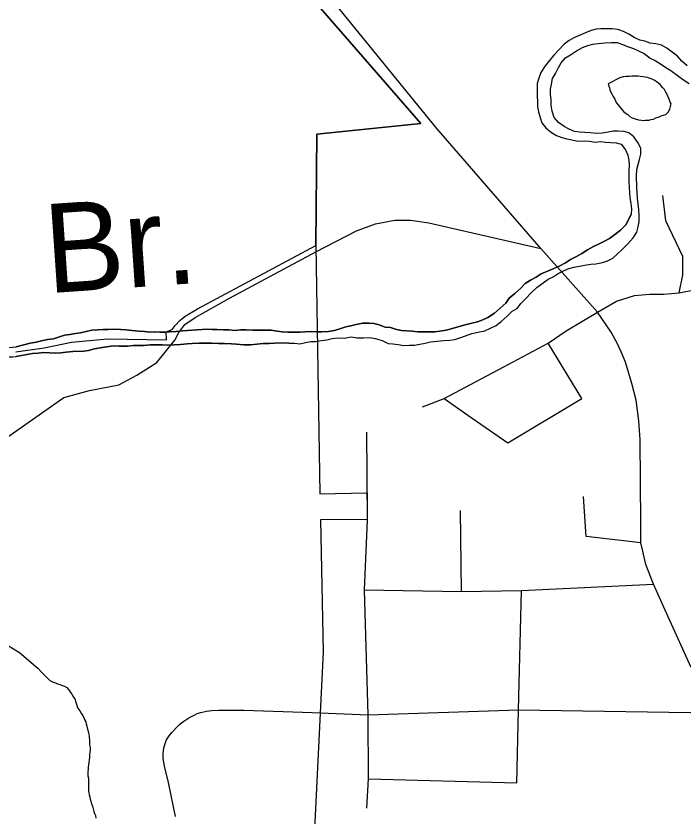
# Model space of a CAD drawing. Extents: x 0 to 44.3, y 0 to 22.
# Drawn here: x 6.753 to 7.465, y 17.047 to 17.9 of the extents above; entities that cross this region are included whole.
import ezdxf

# ---------------------------------------------------------------- set-up
doc = ezdxf.new("R2010")
doc.units = 0
for name, color, linetype in [('GM_X_City_Street', 7, 'Continuous'), ('GM_X_Corporation', 7, 'Continuous'), ('GM_X_Minor_Lake', 7, 'Continuous'), ('GM_X_Minor_River', 7, 'Continuous'), ('GM_X_Minor_River_Text', 7, 'Continuous'), ('GM_X_State_Route', 7, 'Continuous')]:
    doc.layers.add(name, color=color, linetype=linetype)

msp = doc.modelspace()

# ---------------------------------------------------------------- linework, layer by layer
at = {"layer": 'GM_X_City_Street'}
for p, q in [((7.12724, 17.41122), (7.12695, 17.45623)), ((7.22768, 17.28648), (7.22658, 17.37258)), ((7.12878, 17.08658), (7.28653, 17.0823))]:
    msp.add_line(p, q, dxfattribs=at)
for points in [[(7.45977, 17.60465), (7.46347, 17.62393), (7.46345, 17.64339), (7.44532, 17.68153), (7.44219, 17.70849)], [(7.07246, 17.64827), (7.11592, 17.67067), (7.13597, 17.67813), (7.15675, 17.68201), (7.17336, 17.68207), (7.19293, 17.67924), (7.31218, 17.65183)], [(6.92212, 17.55418), (6.92659, 17.5623), (6.93286, 17.57103), (6.94381, 17.57832), (6.98068, 17.59888), (7.07246, 17.64827)], [(7.18604, 17.48326), (7.20918, 17.49199), (7.27207, 17.52551), (7.31997, 17.55123), (7.33909, 17.56424), (7.37276, 17.584)], [(6.30242, 16.8069), (6.63737, 17.15584), (6.69056, 17.36679), (6.69333, 17.3776), (6.70222, 17.39979), (6.7063, 17.40894), (6.71111, 17.41764), (6.72202, 17.43335), (6.72813, 17.44047), (6.73703, 17.44625), (6.80414, 17.49308), (6.83121, 17.5006), (6.86241, 17.50669), (6.88169, 17.51703), (6.90323, 17.53033), (6.92212, 17.55418)], [(7.20918, 17.49199), (7.23431, 17.47423), (7.27695, 17.4449), (7.35592, 17.49195), (7.31997, 17.55123)], [(7.12741, 17.37786), (7.12737, 17.39097), (7.12724, 17.41122)], [(7.41896, 17.33821), (7.36072, 17.34509), (7.35764, 17.38766)], [(7.12695, 17.05542), (7.12878, 17.08658), (7.12817, 17.15502), (7.1245, 17.28821), (7.12746, 17.36257), (7.12741, 17.37786)], [(7.1245, 17.28821), (7.22768, 17.28648), (7.29178, 17.28762), (7.43229, 17.29421)], [(7.28653, 17.0823), (7.28852, 17.16019), (7.29178, 17.28762)], [(6.92286, 17.04654), (6.91542, 17.08269), (6.91132, 17.1002), (6.90967, 17.10849), (6.90986, 17.11364), (6.91065, 17.11967), (6.91257, 17.12643), (6.91308, 17.12754), (6.91415, 17.12949), (6.91619, 17.1325), (6.91911, 17.136), (6.92534, 17.14281), (6.9271, 17.14466), (6.92933, 17.14641), (6.93186, 17.14826), (6.93732, 17.15185), (6.94344, 17.15507), (6.94612, 17.15628), (6.94997, 17.15759), (6.9559, 17.1588), (6.96164, 17.15953), (6.96874, 17.15996), (6.99625, 17.15983), (7.06866, 17.15732)], [(7.06866, 17.15732), (7.12817, 17.15502), (7.28852, 17.16019), (7.49466, 17.15689)]]:
    msp.add_lwpolyline(points, dxfattribs=at)
at = {"layer": 'GM_X_Corporation'}
for points in [[(7.82586, 18.31414), (6.89604, 18.28498), (6.92603, 18.24781), (6.94991, 18.15965), (6.96334, 18.1059), (6.94492, 18.09718), (6.93169, 18.09094), (6.92822, 17.95203), (7.03936, 17.95213), (7.18428, 17.78522), (7.07361, 17.77392), (7.07233, 17.65528), (7.07678, 17.3906), (7.12716, 17.39153), (7.12726, 17.36313), (7.07741, 17.36275), (7.08028, 17.22203), (7.07018, 17.01142)], [(6.75287, 17.54169), (6.78294, 17.54612), (6.81197, 17.55215), (6.85066, 17.55576), (6.91324, 17.55458), (6.91296, 17.5631), (6.91953, 17.56556), (6.92257, 17.56982), (6.92761, 17.57513), (6.93342, 17.58001), (6.94645, 17.58759), (7.07233, 17.65528), (7.07361, 17.77392), (7.18428, 17.78522), (7.03936, 17.95213)], [(6.75287, 17.54169), (6.78294, 17.54612), (6.81197, 17.55215), (6.85066, 17.55576), (6.91324, 17.55458), (6.91296, 17.5631), (6.91953, 17.56556), (6.92257, 17.56982), (6.92761, 17.57513), (6.93342, 17.58001), (6.94645, 17.58759), (7.07233, 17.65528), (7.07678, 17.3906), (7.12716, 17.39153), (7.12726, 17.36313), (7.07741, 17.36275), (7.08028, 17.22203), (7.07018, 17.01142)]]:
    msp.add_lwpolyline(points, dxfattribs=at)
at = {"layer": 'GM_X_Minor_Lake'}
for points in [[(7.39241, 17.80765), (7.40044, 17.79793), (7.40316, 17.79572), (7.40509, 17.79462), (7.40704, 17.79277), (7.40975, 17.79132), (7.41282, 17.79025), (7.41628, 17.7892), (7.41971, 17.7889), (7.42163, 17.78857), (7.42353, 17.78862), (7.42543, 17.78867), (7.42772, 17.78873), (7.4296, 17.78954), (7.43226, 17.78999), (7.43489, 17.79119), (7.43829, 17.79242), (7.44056, 17.79324), (7.44282, 17.79406), (7.44547, 17.79489), (7.44807, 17.79724), (7.4499, 17.80033), (7.45128, 17.80608), (7.45008, 17.80796), (7.44886, 17.81097), (7.44803, 17.81361), (7.44722, 17.8155), (7.44562, 17.8185), (7.44402, 17.82151), (7.44206, 17.82374), (7.43932, 17.82672), (7.43504, 17.83003), (7.4331, 17.83151), (7.43001, 17.83295), (7.42771, 17.83366), (7.42579, 17.83437), (7.42387, 17.8347), (7.4212, 17.83502), (7.41814, 17.83532), (7.41547, 17.83563), (7.41242, 17.83555), (7.40938, 17.83547), (7.40633, 17.8354), (7.40329, 17.83532), (7.39987, 17.83485), (7.39646, 17.834), (7.38406, 17.8276)], [(7.38406, 17.8276), (7.38448, 17.82608), (7.38532, 17.82306), (7.38575, 17.82117), (7.38696, 17.81853), (7.38816, 17.81628), (7.38936, 17.81402), (7.39096, 17.81102), (7.39241, 17.80765)]]:
    msp.add_lwpolyline(points, dxfattribs=at)
at = {"layer": 'GM_X_Minor_River'}
for points in [[(7.46828, 17.84656), (7.46257, 17.85148), (7.45801, 17.85679), (7.45231, 17.86133), (7.4466, 17.86549), (7.44091, 17.86852), (7.43483, 17.87002), (7.42876, 17.87076), (7.42307, 17.87303), (7.41776, 17.87415), (7.41168, 17.8768), (7.40598, 17.88058), (7.40028, 17.88323), (7.39421, 17.88549), (7.38814, 17.88624), (7.37638, 17.88621), (7.37107, 17.88581), (7.36577, 17.88428), (7.35971, 17.88199), (7.34759, 17.87664), (7.34229, 17.87359), (7.33699, 17.86978), (7.3317, 17.86408), (7.32602, 17.85799), (7.31695, 17.84657), (7.31242, 17.83973), (7.31017, 17.83365), (7.30828, 17.82795), (7.30832, 17.81428), (7.30872, 17.8082), (7.30874, 17.80289), (7.30989, 17.79758), (7.31142, 17.7915), (7.31333, 17.78581), (7.31752, 17.78051), (7.3236, 17.77558), (7.32892, 17.77256), (7.33462, 17.77029), (7.33993, 17.76879), (7.35207, 17.76654), (7.35852, 17.76656), (7.36421, 17.76619), (7.37028, 17.76545), (7.37597, 17.76584), (7.38128, 17.76547), (7.39266, 17.76474), (7.39797, 17.76323), (7.40254, 17.75717), (7.40483, 17.75148), (7.40599, 17.74617), (7.40638, 17.74085), (7.40602, 17.73515), (7.40605, 17.723), (7.40724, 17.70592), (7.40802, 17.69985), (7.40879, 17.69415), (7.40843, 17.68846)], [(7.32458, 17.8333), (7.32797, 17.83863), (7.33099, 17.84471), (7.33401, 17.85003), (7.33855, 17.85536), (7.34385, 17.85841), (7.35028, 17.8626), (7.35672, 17.86603), (7.3624, 17.86833), (7.36771, 17.86986), (7.37339, 17.87063), (7.3806, 17.87103), (7.38742, 17.87142), (7.39349, 17.87144), (7.39919, 17.86955), (7.40564, 17.86691), (7.41096, 17.86503), (7.41703, 17.86238), (7.42235, 17.85974), (7.42881, 17.85482), (7.43413, 17.85217), (7.43983, 17.84877), (7.44553, 17.84499), (7.45085, 17.84158), (7.45769, 17.83666), (7.46339, 17.8325), (7.47023, 17.82796)], [(7.0436, 17.55089), (7.04967, 17.5509), (7.05536, 17.55053), (7.06142, 17.55169), (7.06711, 17.55284), (7.07242, 17.55285), (7.07848, 17.55401), (7.08417, 17.55478), (7.08985, 17.55593), (7.09592, 17.55671), (7.10313, 17.55635), (7.11033, 17.55788), (7.1164, 17.55676), (7.12323, 17.55677), (7.13005, 17.55717), (7.13574, 17.55604), (7.14333, 17.55378), (7.14941, 17.55076), (7.15472, 17.55039), (7.16041, 17.54965), (7.16611, 17.54852), (7.17179, 17.54892), (7.17748, 17.54893), (7.18317, 17.55008), (7.18885, 17.55124), (7.19454, 17.55239), (7.20895, 17.55394), (7.21539, 17.55434), (7.2207, 17.55511), (7.226, 17.55664), (7.23207, 17.55893), (7.23889, 17.56123), (7.24685, 17.56314), (7.25253, 17.5643), (7.25859, 17.56697), (7.26465, 17.57002), (7.26995, 17.57421), (7.27638, 17.57992), (7.28167, 17.58525), (7.28698, 17.58792), (7.29113, 17.59325), (7.29643, 17.59858), (7.3021, 17.60467), (7.30853, 17.61076), (7.31458, 17.61533), (7.32026, 17.61914), (7.32556, 17.62181), (7.33086, 17.62524), (7.33654, 17.62829), (7.34222, 17.63058), (7.34753, 17.63211), (7.3536, 17.63327), (7.3589, 17.63404), (7.36572, 17.63519), (7.37103, 17.63559), (7.37785, 17.63712), (7.38316, 17.63865), (7.38884, 17.64171), (7.39414, 17.64628), (7.39943, 17.65122), (7.4051, 17.65693), (7.41078, 17.6634), (7.41455, 17.66949), (7.41605, 17.67519), (7.41717, 17.6805), (7.41716, 17.68696), (7.41676, 17.69303), (7.41598, 17.69949), (7.41521, 17.70556), (7.41481, 17.71164), (7.41442, 17.71695), (7.41438, 17.72948), (7.41474, 17.73632), (7.41586, 17.74163), (7.41736, 17.74695), (7.41886, 17.75265), (7.41885, 17.75873), (7.41579, 17.76479), (7.41123, 17.77086), (7.4059, 17.7754), (7.40059, 17.77653), (7.39452, 17.77689), (7.38921, 17.77688), (7.3839, 17.77611), (7.37746, 17.77496), (7.37139, 17.77456), (7.36532, 17.77531), (7.35925, 17.77567), (7.35356, 17.77604), (7.34825, 17.77678), (7.34256, 17.77905), (7.33724, 17.78207), (7.33116, 17.78624), (7.32659, 17.79154), (7.3243, 17.79837), (7.32314, 17.80482), (7.32313, 17.81052), (7.32273, 17.81659), (7.32271, 17.82191), (7.32346, 17.82723), (7.32458, 17.8333)], [(7.40843, 17.68846), (7.40579, 17.68238), (7.40277, 17.67705), (7.3971, 17.67134), (7.39104, 17.66677), (7.38537, 17.66258), (7.37931, 17.65953), (7.37363, 17.65648), (7.36832, 17.65419), (7.36189, 17.65037), (7.35583, 17.64656), (7.35015, 17.64351), (7.34371, 17.64008), (7.33842, 17.63665), (7.33198, 17.63321), (7.32554, 17.63016), (7.31266, 17.62482), (7.30736, 17.62139), (7.3013, 17.61833), (7.29562, 17.61452), (7.29071, 17.6092), (7.28465, 17.60386), (7.2786, 17.59891), (7.27482, 17.59359), (7.26272, 17.58293), (7.2559, 17.57836), (7.2506, 17.57606), (7.24492, 17.57377), (7.23885, 17.57224), (7.23014, 17.57032), (7.22407, 17.56841), (7.21763, 17.56687), (7.21157, 17.56496), (7.20475, 17.5638), (7.19944, 17.56303), (7.18161, 17.56299), (7.17479, 17.56373), (7.16948, 17.5641), (7.16378, 17.56446), (7.15847, 17.56559), (7.15202, 17.56785), (7.14633, 17.56822), (7.13987, 17.57048), (7.13418, 17.57199), (7.12887, 17.57235), (7.12242, 17.57234), (7.1156, 17.5708), (7.10992, 17.56965), (7.10461, 17.5685), (7.09931, 17.56659), (7.09249, 17.56467), (7.08604, 17.56352), (7.07884, 17.56312), (7.07353, 17.56311), (7.0667, 17.56347), (7.06063, 17.56308), (7.05532, 17.56268), (7.04281, 17.56265), (7.03674, 17.56302), (7.03143, 17.56377), (7.02498, 17.56489), (7.00526, 17.56484), (6.99805, 17.56521), (6.99236, 17.56519), (6.98667, 17.56442), (6.97984, 17.56516), (6.97416, 17.56515), (6.96733, 17.56551), (6.96202, 17.5655), (6.95633, 17.56586), (6.93585, 17.56468), (6.93054, 17.56428), (6.92372, 17.56351), (6.91689, 17.56311), (6.91159, 17.56272), (6.90628, 17.56271), (6.90097, 17.56307), (6.89566, 17.56268), (6.88997, 17.56343), (6.8839, 17.56379), (6.87669, 17.56453), (6.87024, 17.56528), (6.86455, 17.56564), (6.85696, 17.566), (6.85128, 17.56561), (6.84597, 17.5656), (6.84028, 17.56521), (6.83383, 17.56481), (6.82777, 17.56366), (6.82171, 17.56212), (6.8164, 17.56135), (6.81033, 17.5602), (6.80465, 17.55943), (6.79821, 17.55751), (6.7929, 17.5556), (6.78646, 17.55482), (6.78001, 17.55367), (6.77433, 17.55214), (6.76826, 17.55098), (6.753, 17.54701)], [(6.7532, 17.54706), (6.76826, 17.55098), (6.77433, 17.55214), (6.78001, 17.55367), (6.78646, 17.55482), (6.7929, 17.5556), (6.79821, 17.55751), (6.80465, 17.55943), (6.81033, 17.5602), (6.8164, 17.56135), (6.82171, 17.56212), (6.82777, 17.56366), (6.83383, 17.56481), (6.84028, 17.56521), (6.84597, 17.5656), (6.85128, 17.56561), (6.85696, 17.566), (6.86455, 17.56564), (6.87024, 17.56528), (6.87669, 17.56453), (6.8839, 17.56379), (6.88997, 17.56343), (6.89566, 17.56268), (6.90097, 17.56307), (6.90628, 17.56271), (6.91159, 17.56272), (6.91689, 17.56311), (6.92372, 17.56351), (6.93054, 17.56428), (6.93585, 17.56468), (6.95633, 17.56586), (6.96202, 17.5655), (6.96733, 17.56551), (6.97416, 17.56515), (6.97984, 17.56516), (6.98667, 17.56442), (6.99236, 17.56519), (6.99805, 17.56521), (7.00526, 17.56484), (7.02498, 17.56489), (7.03143, 17.56377), (7.03674, 17.56302), (7.04281, 17.56265), (7.05532, 17.56268), (7.06063, 17.56308), (7.0667, 17.56347), (7.07353, 17.56311), (7.07884, 17.56312), (7.08604, 17.56352), (7.09249, 17.56467), (7.09931, 17.56659), (7.10461, 17.5685), (7.10992, 17.56965), (7.1156, 17.5708), (7.12242, 17.57234), (7.12887, 17.57235), (7.13418, 17.57199), (7.13987, 17.57048), (7.14633, 17.56822), (7.15202, 17.56785), (7.15847, 17.56559), (7.16378, 17.56446), (7.16948, 17.5641), (7.17479, 17.56373), (7.18161, 17.56299), (7.19944, 17.56303), (7.20475, 17.5638), (7.21157, 17.56496), (7.21763, 17.56687), (7.22407, 17.56841), (7.23014, 17.57032), (7.23885, 17.57224), (7.24492, 17.57377), (7.2506, 17.57606), (7.2559, 17.57836), (7.26272, 17.58293), (7.27482, 17.59359), (7.2786, 17.59891), (7.28465, 17.60386), (7.29071, 17.6092), (7.29562, 17.61452), (7.3013, 17.61833), (7.30736, 17.62139), (7.31266, 17.62482), (7.32554, 17.63016), (7.33198, 17.63321), (7.33842, 17.63665), (7.34371, 17.64008), (7.35015, 17.64351), (7.35583, 17.64656), (7.36189, 17.65037), (7.36832, 17.65419), (7.37363, 17.65648), (7.37931, 17.65953), (7.38537, 17.66258), (7.39104, 17.66677), (7.3971, 17.67134), (7.40277, 17.67705), (7.40579, 17.68238), (7.40843, 17.68846)], [(6.75298, 17.53682), (6.77057, 17.53998), (6.77664, 17.54037), (6.7827, 17.54115), (6.78877, 17.54078), (6.79522, 17.54042), (6.80091, 17.54081), (6.80659, 17.54158), (6.81342, 17.54236), (6.82479, 17.54239), (6.8301, 17.54316), (6.83654, 17.54507), (6.84488, 17.54661), (6.85702, 17.54816), (6.86308, 17.54779), (6.87181, 17.54781), (6.87787, 17.54859), (6.88887, 17.54861), (6.89607, 17.54939), (6.90252, 17.54941), (6.90859, 17.54942), (6.91466, 17.54906), (6.92148, 17.54945), (6.92831, 17.54947), (6.93551, 17.55025), (6.94082, 17.55064), (6.94803, 17.55103), (6.9613, 17.55107), (6.96889, 17.55071), (6.97533, 17.55072), (6.98254, 17.55036), (6.98785, 17.54999), (6.99582, 17.54925), (7.00302, 17.54927), (7.00947, 17.55004), (7.01629, 17.55082), (7.02274, 17.55083), (7.02881, 17.55123), (7.03564, 17.55125), (7.0436, 17.55089)], [(7.0436, 17.55089), (7.03564, 17.55125), (7.02881, 17.55123), (7.02274, 17.55083), (7.01629, 17.55082), (7.00947, 17.55004), (7.00302, 17.54927), (6.99582, 17.54925), (6.98785, 17.54999), (6.98254, 17.55036), (6.97533, 17.55072), (6.96889, 17.55071), (6.9613, 17.55107), (6.94803, 17.55103), (6.94082, 17.55064), (6.93551, 17.55025), (6.92831, 17.54947), (6.92148, 17.54945), (6.91466, 17.54906), (6.90859, 17.54942), (6.90252, 17.54941), (6.89607, 17.54939), (6.88887, 17.54861), (6.87787, 17.54859), (6.87181, 17.54781), (6.86308, 17.54779), (6.85702, 17.54816), (6.84488, 17.54661), (6.83654, 17.54507), (6.8301, 17.54316), (6.82479, 17.54239), (6.81342, 17.54236), (6.80659, 17.54158), (6.80091, 17.54081), (6.79522, 17.54042), (6.78877, 17.54078), (6.7827, 17.54115), (6.77664, 17.54037), (6.77057, 17.53998), (6.75333, 17.53688)], [(6.73546, 17.23416), (6.75668, 17.22139)], [(6.75668, 17.22139), (6.77614, 17.20476), (6.7804, 17.19988), (6.78504, 17.19539), (6.7889, 17.19164), (6.79196, 17.19016), (6.79502, 17.18907), (6.79732, 17.18796), (6.79961, 17.18723), (6.80152, 17.1865), (6.80458, 17.18541), (6.80726, 17.18393), (6.80998, 17.18054), (6.81115, 17.17866), (6.81232, 17.17678), (6.81427, 17.17376), (6.81582, 17.17188), (6.81664, 17.16847), (6.81743, 17.1662), (6.81823, 17.16393), (6.81902, 17.16204), (6.82097, 17.15903), (6.82292, 17.15602), (6.82409, 17.15413), (6.82566, 17.15111), (6.82645, 17.14922), (6.82724, 17.14734), (6.82765, 17.14544), (6.82846, 17.14279), (6.82927, 17.13976), (6.83009, 17.13597), (6.83092, 17.1318), (6.83137, 17.12724), (6.83144, 17.12306), (6.83187, 17.12003), (6.83191, 17.11737), (6.83158, 17.1147), (6.83124, 17.11203), (6.83128, 17.10937), (6.83027, 17.10175), (6.82993, 17.09946), (6.82997, 17.09718), (6.82964, 17.09414), (6.82971, 17.08995), (6.83013, 17.0873), (6.83018, 17.08388), (6.83024, 17.08046), (6.83028, 17.07818), (6.83032, 17.07551), (6.83035, 17.07361), (6.83076, 17.07172), (6.8308, 17.06982), (6.83159, 17.06755), (6.83202, 17.06489), (6.83281, 17.063), (6.83362, 17.05997), (6.83441, 17.0577), (6.83522, 17.05467), (6.83603, 17.05202), (6.83682, 17.04975), (6.83762, 17.04748), (6.83805, 17.04483)]]:
    msp.add_lwpolyline(points, dxfattribs=at)
for points in [[(6.37483, 17.23671), (6.385, 17.25741), (6.38772, 17.26383), (6.39006, 17.26987), (6.39316, 17.27553), (6.39853, 17.28154), (6.40429, 17.28831), (6.41003, 17.29318), (6.41842, 17.29726), (6.42527, 17.29984), (6.43173, 17.30166), (6.43855, 17.30158), (6.44501, 17.30227), (6.4507, 17.30258), (6.45676, 17.30251), (6.46472, 17.30204), (6.47153, 17.30082), (6.47758, 17.29962), (6.48478, 17.29877), (6.49121, 17.29832), (6.4969, 17.29788), (6.50371, 17.29704), (6.50939, 17.29584), (6.51545, 17.29539), (6.52189, 17.29493), (6.52755, 17.29297), (6.53436, 17.29137), (6.54004, 17.29131), (6.54649, 17.29123), (6.55218, 17.29193), (6.55826, 17.293), (6.57123, 17.30044), (6.57546, 17.30609), (6.57781, 17.31251), (6.57901, 17.31819), (6.57945, 17.32388), (6.57914, 17.33034), (6.57844, 17.33604), (6.57701, 17.34364), (6.57555, 17.34936), (6.57448, 17.35544), (6.57341, 17.36114), (6.57197, 17.368), (6.57242, 17.3752), (6.57211, 17.3809), (6.57255, 17.38697), (6.57339, 17.39379), (6.57497, 17.4006), (6.57618, 17.40666), (6.57739, 17.41386), (6.57822, 17.4203), (6.57904, 17.42599), (6.58063, 17.43242), (6.5826, 17.43885), (6.58456, 17.4449), (6.58803, 17.45094), (6.59113, 17.45659), (6.5969, 17.46488), (6.60114, 17.47052), (6.60613, 17.47654), (6.61188, 17.48217), (6.61688, 17.48856), (6.62187, 17.49458), (6.62799, 17.49982), (6.64174, 17.50877), (6.64749, 17.51516), (6.65824, 17.52718), (6.66474, 17.53242), (6.67087, 17.53843), (6.67659, 17.54102), (6.68268, 17.54322), (6.69065, 17.54427), (6.69634, 17.54459), (6.70317, 17.54489), (6.70922, 17.54406), (6.71529, 17.54399), (6.7225, 17.54467), (6.7532, 17.54703)], [(6.39465, 17.23695), (6.40592, 17.26362), (6.41015, 17.26964), (6.41629, 17.27603), (6.42393, 17.28163), (6.43041, 17.28497), (6.43726, 17.28679), (6.44447, 17.28747), (6.45281, 17.28737), (6.46038, 17.28691), (6.46644, 17.28646), (6.47629, 17.28559), (6.48273, 17.28513), (6.48955, 17.28468), (6.49598, 17.28346), (6.50204, 17.28225), (6.50771, 17.28105), (6.51338, 17.27947), (6.52171, 17.27823), (6.53042, 17.27775), (6.53875, 17.27728), (6.54671, 17.27681), (6.55316, 17.27673), (6.56036, 17.27703), (6.56682, 17.2781), (6.57405, 17.28067), (6.58017, 17.28592), (6.58516, 17.29155), (6.58939, 17.2972), (6.59135, 17.30325), (6.59332, 17.30968), (6.59269, 17.32183), (6.592, 17.32791), (6.59058, 17.33666), (6.58875, 17.34275), (6.58767, 17.34846), (6.58699, 17.35454), (6.58629, 17.36024), (6.5856, 17.36708), (6.5853, 17.37429), (6.58501, 17.38189), (6.58547, 17.38947), (6.58667, 17.39553), (6.58826, 17.40197), (6.59179, 17.41256), (6.59336, 17.41823), (6.5957, 17.42428), (6.59767, 17.43109), (6.60155, 17.43863), (6.60389, 17.44468), (6.60737, 17.45109), (6.61008, 17.45676), (6.61432, 17.4624), (6.61931, 17.4688), (6.62468, 17.47443), (6.63157, 17.48042), (6.63657, 17.48682), (6.64119, 17.49322), (6.64544, 17.50038), (6.65847, 17.51314), (6.66497, 17.51876), (6.67069, 17.52211), (6.67869, 17.52543), (6.68441, 17.52802), (6.69089, 17.53098), (6.70381, 17.53387), (6.70988, 17.53418), (6.71633, 17.53487), (6.7224, 17.53518), (6.75333, 17.53684)]]:
    msp.add_spline(points, degree=3, dxfattribs=at)
at = {"layer": 'GM_X_State_Route'}
for points in [[(7.42096, 17.32928), (7.41896, 17.33821), (7.41896, 17.35925), (7.41815, 17.44855), (7.41674, 17.46823), (7.41403, 17.49041), (7.40931, 17.50798), (7.40264, 17.53064), (7.39803, 17.54176), (7.39369, 17.55108), (7.38707, 17.5627), (7.37276, 17.584), (7.31218, 17.65183), (7.30813, 17.65678), (7.2016, 17.77988), (7.07813, 17.93161)], [(7.42946, 17.60338), (7.44335, 17.60338), (7.45977, 17.60465), (7.47771, 17.60825), (7.50395, 17.61421), (7.55617, 17.62665)], [(7.37276, 17.584), (7.39303, 17.59581), (7.41223, 17.60176), (7.42847, 17.60338), (7.42946, 17.60338)], [(7.47261, 17.20549), (7.44781, 17.25926), (7.43229, 17.29421), (7.42417, 17.315), (7.42096, 17.32928)]]:
    msp.add_lwpolyline(points, dxfattribs=at)

# ---------------------------------------------------------------- texts
at = {"layer": 'GM_X_Minor_River_Text'}
msp.add_text('Br.', height=0.094765, rotation=3.92579, dxfattribs=at).set_placement((6.78654, 17.6042))

doc.saveas('drawing.dxf')
